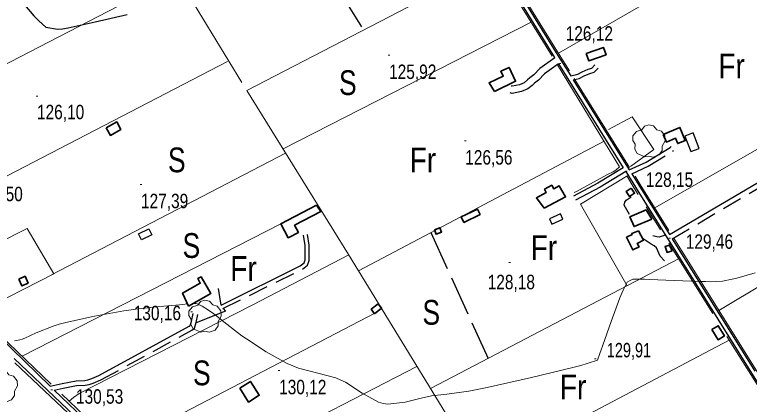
# Model space of a CAD drawing. Extents: x 487425 to 492029, y 4383576 to 4386788.
# Drawn here: x 489846.1 to 490290.9, y 4385229.4 to 4385465.2 of the extents above; entities that cross this region are included whole.
import ezdxf
from ezdxf.enums import TextEntityAlignment as Align

# ---------------------------------------------------------------- set-up
doc = ezdxf.new("R2010")
doc.units = 0
doc.header["$LTSCALE"] = 4
doc.linetypes.add('LONG_DASHED', pattern=[7.5, 6, -1.5])
doc.linetypes.add('MEDIUM_DASHED', pattern=[4.5, 3, -1.5])
for name, color, linetype, lineweight in [('21', 7, 'Continuous', 25), ('25', 7, 'LONG_DASHED', 25), ('29', 7, 'Continuous', 13), ('38', 7, 'Continuous', 25), ('47', 7, 'Continuous', 35), ('48', 7, 'MEDIUM_DASHED', 25), ('51', 7, 'Continuous', 13), ('7', 7, 'Continuous', 13), ('8', 7, 'Continuous', 25), ('9', 7, 'Continuous', 13)]:
    doc.layers.add(name, color=color, linetype=linetype, lineweight=lineweight)
doc.layers.add('31', color=7, linetype='Continuous')

msp = doc.modelspace()

# ---------------------------------------------------------------- linework, layer by layer
at = {"layer": '21'}
for points in [[(490251.81, 4385391.69), (490255.52, 4385382.34), (490260.49, 4385384.31), (490256.78, 4385393.66)], [(490176.54, 4385344.68), (490169.9, 4385341.62), (490171.35, 4385338.47), (490177.99, 4385341.53)]]:
    msp.add_lwpolyline(points, close=True, dxfattribs=at)
at = {"layer": '25'}
for p, q in [((489995.92, 4385554.6), (490057.22, 4385455.91)), ((490098.1, 4385333.38), (490132.67, 4385257.15))]:
    msp.add_line(p, q, dxfattribs=at)
at = {"layer": '29'}
for points in [[(490227.61, 4385379.12), (490223.07, 4385381.24), (490221.66, 4385383.78), (490221.76, 4385386.76), (490220.39, 4385389.17), (490220.43, 4385391.92), (490222.59, 4385394.52), (490225.78, 4385395.52), (490227.43, 4385397.71), (490230, 4385398.54), (490232.86, 4385397.89), (490234.81, 4385395.62), (490237.62, 4385394.8), (490239.75, 4385391.95), (490239.99, 4385388.82), (490238.11, 4385385.67), (490238.11, 4385382.99), (490236.29, 4385380.38), (490232.67, 4385379.04), (490229.9, 4385379.67)], [(489958.78, 4385273.08), (489954.24, 4385275.2), (489952.83, 4385277.74), (489952.93, 4385280.72), (489951.56, 4385283.13), (489951.6, 4385285.88), (489953.76, 4385288.48), (489956.95, 4385289.48), (489958.6, 4385291.67), (489961.17, 4385292.5), (489964.03, 4385291.85), (489965.98, 4385289.58), (489968.79, 4385288.76), (489970.92, 4385285.91), (489971.16, 4385282.78), (489969.28, 4385279.63), (489969.28, 4385276.95), (489967.46, 4385274.34), (489963.84, 4385273), (489961.07, 4385273.63)], [(489835.46, 4385230.87), (489830.92, 4385232.99), (489829.51, 4385235.53), (489829.61, 4385238.51), (489828.24, 4385240.92), (489828.28, 4385243.67), (489830.44, 4385246.27), (489833.63, 4385247.27), (489835.28, 4385249.46), (489837.85, 4385250.29), (489840.71, 4385249.64), (489842.66, 4385247.37), (489845.47, 4385246.55), (489847.6, 4385243.7), (489847.84, 4385240.57), (489845.96, 4385237.42), (489845.96, 4385234.74), (489844.14, 4385232.13), (489840.52, 4385230.79), (489837.75, 4385231.42)]]:
    msp.add_lwpolyline(points, close=True, dxfattribs=at)
at = {"layer": '38'}
for p, q in [((490175.43, 4385435.47), (490214.59, 4385372.6)), ((490184.26, 4385425.73), (490218.21, 4385371.23)), ((490244.19, 4385329.63), (490294.23, 4385249.56)), ((489971.09, 4385289.49), (489969.53, 4385299.42)), ((489836.23, 4385270.76), (489867.55, 4385240.41))]:
    msp.add_line(p, q, dxfattribs=at)
for points in [[(490091.34, 4385571.41), (490173.01, 4385439.35), (490173.19, 4385439.06)], [(490093.86, 4385571.79), (490175, 4385440.59), (490182.73, 4385428.18)], [(490173.19, 4385439.06), (490164.14, 4385432.69), (490160.43, 4385428.77), (490158.09, 4385426.95), (490156.66, 4385425.69), (490154.55, 4385424.06), (490151.66, 4385422.7), (490147.29, 4385421.91), (490146.71, 4385422.01)], [(490182.73, 4385428.18), (490186.96, 4385429.26), (490189.68, 4385430.68), (490193.37, 4385432.16), (490195.44, 4385432.88), (490197.31, 4385434.8)], [(490242.52, 4385332.29), (490309.11, 4385371.4), (490329.79, 4385383.31), (490335.95, 4385385.53), (490339.74, 4385386.46), (490342.83, 4385388.24)], [(490218.21, 4385371.23), (490228.37, 4385375.89), (490242.9, 4385384.93), (490243.56, 4385385.36)], [(490214.59, 4385372.6), (490199.14, 4385363.31), (490184.37, 4385355.43)], [(490216.06, 4385370.24), (490200.52, 4385360.89), (490185.68, 4385352.97)], [(490216.06, 4385370.24), (490221.96, 4385360.77), (490297.32, 4385240.19), (490301.58, 4385233.46)], [(490219.68, 4385368.86), (490223.95, 4385362.01), (490242.52, 4385332.29)], [(490218.3, 4385344.25), (490215.17, 4385349.96), (490215.47, 4385351.68), (490216.38, 4385352.88), (490219.31, 4385354.97)], [(489971.09, 4385289.49), (490019.01, 4385313.15), (490021.37, 4385315.09), (490022.03, 4385316.84), (490021.98, 4385325.6), (490021.03, 4385331.78)], [(490239.96, 4385331.89), (490236.33, 4385330.55), (490234.98, 4385330.71), (490232.43, 4385331.31)], [(490239.44, 4385316.22), (490236.97, 4385319.15), (490234.74, 4385324.18), (490233.17, 4385325.39), (490231.44, 4385326.37), (490226.06, 4385329.91)], [(489972.41, 4385287.51), (489973.84, 4385285.83), (489955.9, 4385278.66)], [(489867.55, 4385240.41), (489874.85, 4385242.08), (489883.26, 4385243.72), (489888.5, 4385243.86), (489890.41, 4385244.27), (489892.74, 4385244.99), (489897.09, 4385246.81), (489951.74, 4385276.67), (489952.43, 4385277.2), (489953.18, 4385279.58), (489954.08, 4385284.33)], [(489845.84, 4385257.08), (489890.1, 4385215.01), (489915.19, 4385191.17)], [(489870.05, 4385238.03), (489892.11, 4385217.12), (489919.37, 4385191.22)]]:
    msp.add_lwpolyline(points, dxfattribs=at)
at = {"layer": '38', "linetype": 'MEDIUM_DASHED'}
for points in [[(490175.43, 4385435.47), (490166.93, 4385429.47), (490163.29, 4385425.62), (490160.8, 4385423.69), (490159.36, 4385422.41), (490156.77, 4385420.42), (490152.97, 4385418.62), (490147.32, 4385417.61), (490146.02, 4385417.82)], [(490184.26, 4385425.73), (490187.95, 4385426.68), (490190.83, 4385428.18), (490194.33, 4385429.58), (490196.96, 4385430.5), (490199.28, 4385432.88)], [(490244.19, 4385329.63), (490310.69, 4385368.69), (490331.11, 4385380.46), (490336.85, 4385382.52), (490340.92, 4385383.53), (490344.39, 4385385.52)], [(490219.68, 4385368.86), (490229.68, 4385373.46), (490244.39, 4385382.61), (490245.07, 4385383.05)], [(489972.14, 4385287.38), (490020.29, 4385311.17), (490023.35, 4385313.67), (490024.38, 4385316.43), (490024.32, 4385325.78), (490023.36, 4385332.14)], [(489870.05, 4385238.03), (489875.44, 4385239.27), (489883.58, 4385240.85), (489888.85, 4385240.99), (489891.14, 4385241.49), (489893.72, 4385242.28), (489898.34, 4385244.22), (489953.31, 4385274.25), (489954.9, 4385275.47), (489955.97, 4385278.89), (489956.9, 4385283.8)]]:
    msp.add_lwpolyline(points, dxfattribs=at)
at = {"layer": '47'}
for points in [[(490192.05, 4385441.73), (490202.55, 4385445.41), (490204.12, 4385440.94), (490193.62, 4385437.26)], [(490136.5, 4385418.81), (490149.41, 4385424.91), (490145.42, 4385433.33), (490140.45, 4385430.98), (490141.85, 4385428), (490133.33, 4385424.01)], [(489901.52, 4385396.65), (489907.88, 4385400.28), (489910.44, 4385395.79), (489904.08, 4385392.16)], [(490238.69, 4385392.78), (490248.9, 4385396.95), (490252.12, 4385389.06), (490247.58, 4385387.21), (490246.26, 4385390.42), (490240.69, 4385388.13)], [(490166.65, 4385348.08), (490179.64, 4385354.94), (490175.8, 4385361.6), (490172.54, 4385359.74), (490171.23, 4385362.02), (490166.89, 4385359.54), (490167.94, 4385357.69), (490161.95, 4385354.31)], [(490219.4, 4385360.3), (490221.41, 4385357.19), (490218.33, 4385355.2), (490216.32, 4385358.31)], [(490028.84, 4385349.85), (490007.29, 4385338.67), (490011.67, 4385330.21), (490017.86, 4385333.42), (490015.59, 4385337.79), (490031.44, 4385346.04)], [(490116.47, 4385342.84), (490126.27, 4385347.61), (490127.88, 4385344.3), (490118.08, 4385339.53)], [(490231.94, 4385341.51), (490221.13, 4385336.97), (490218.61, 4385342.96), (490228.37, 4385347.08)], [(490100.25, 4385334.94), (490103.59, 4385336.24), (490104.6, 4385333.65), (490101.26, 4385332.35)], [(490223.82, 4385334.49), (490226.73, 4385328.71), (490223.01, 4385326.83), (490224.09, 4385324.67), (490220.4, 4385322.83), (490216.55, 4385330.54), (490219.95, 4385332.25), (490219.65, 4385332.83)], [(490244.25, 4385322.36), (490241.1, 4385321.32), (490239.92, 4385324.89), (490242.62, 4385325.8)], [(489848.62, 4385305.26), (489850.46, 4385301.13), (489854.22, 4385302.8), (489852.38, 4385306.93)], [(489951.36, 4385288.82), (489964.8, 4385296.43), (489959, 4385306.66), (489956.93, 4385305.5), (489958.49, 4385302.69), (489947.78, 4385296.75)], [(490063.96, 4385284.29), (490068.25, 4385287.55), (490066.23, 4385290.2), (490061.94, 4385286.94)], [(490268.18, 4385274.67), (490271.93, 4385268.47), (490275.81, 4385270.82), (490272.06, 4385277.02)], [(489982.32, 4385239.17), (489987.61, 4385230.8), (489994.16, 4385234.94), (489988.87, 4385243.31)]]:
    msp.add_lwpolyline(points, close=True, dxfattribs=at)
at = {"layer": '48'}
msp.add_lwpolyline([(489921.12, 4385332.63), (489927.34, 4385335.71), (489929.14, 4385332.08), (489922.92, 4385329)], close=True, dxfattribs=at)
at = {"layer": '51'}
for p, q in [((490091.15, 4385570.04), (490171.46, 4385440.19)), ((490175.37, 4385441.84), (490347.68, 4385541.46)), ((490158.83, 4385460.62), (490008.61, 4385383.94)), ((490233.65, 4385348.33), (490405.94, 4385447.02)), ((489773.46, 4385332.53), (489975.03, 4385436.91)), ((490212.32, 4385373.21), (490174.74, 4385434.91)), ((490218.36, 4385372.83), (490184.87, 4385426.58)), ((490202.92, 4385388.67), (490054.25, 4385310.24)), ((490010.13, 4385381.49), (489868.42, 4385307.8)), ((490391.9, 4385357.72), (490272.47, 4385286.22)), ((490237, 4385335.06), (490228.38, 4385348.85)), ((490007.29, 4385338.67), (489850.57, 4385258.5)), ((490268.7, 4385284.33), (490242.12, 4385326.86)), ((490248.04, 4385317.41), (490097.87, 4385238.96)), ((490064.57, 4385284.75), (489908.38, 4385203.59)), ((489868.22, 4385241.69), (489836.92, 4385271.49)), ((490129.55, 4385189.79), (490278.74, 4385268.28)), ((489938.76, 4385174.74), (490089.68, 4385252.35))]:
    msp.add_line(p, q, dxfattribs=at)
for points in [[(490094.71, 4385572.25), (490175.82, 4385441.1), (490181.98, 4385431.23)], [(490136.32, 4385497.01), (489986.69, 4385419.26), (490048.17, 4385320.17), (490113.16, 4385213.96), (490134.81, 4385182.02)], [(489831.21, 4385430.37), (489944.24, 4385488.89), (489983.56, 4385424.14)], [(490205.56, 4385395.8), (490219.9, 4385403.48), (490233.04, 4385383.65), (490218.84, 4385373.34)], [(490212.32, 4385373.21), (490210.06, 4385371.2), (490208.41, 4385370.15), (490205.1, 4385368.51), (490186.33, 4385358.22), (490184.83, 4385357.63)], [(490216.93, 4385301.16), (490188.7, 4385350.64), (490216.7, 4385367.57)], [(490223.66, 4385356.39), (490221.21, 4385360.3), (490216.62, 4385367.68)], [(490242.23, 4385334.59), (490224.77, 4385362.52), (490221.71, 4385367.44)], [(489799.67, 4385308.52), (489853.69, 4385335.81), (489869.74, 4385308.47), (489823.71, 4385285.06)], [(490314.35, 4385219.45), (490300.12, 4385241.95), (490245.13, 4385329.96)], [(489879.19, 4385231.29), (489881.68, 4385233.63), (489885.06, 4385236.01), (489989.97, 4385289.46), (490048.33, 4385319.92)], [(490299.79, 4385234.65), (490296.58, 4385239.72), (490277.3, 4385270.57)], [(489846.26, 4385254.56), (489889.09, 4385213.94), (489903.16, 4385200.59)], [(489874.63, 4385235.61), (489893.06, 4385218.12), (489918.13, 4385194.32)]]:
    msp.add_lwpolyline(points, dxfattribs=at)
at = {"layer": '7'}
for p, q in [((490072.26, 4385440.67), (490073.26, 4385440.67)), ((490175.86, 4385435.63), (490176.86, 4385435.63)), ((489859.09, 4385415.89), (489860.09, 4385415.89)), ((490118.36, 4385388.87), (490119.36, 4385388.87)), ((490215.93, 4385370.5), (490216.93, 4385370.5)), ((489922.06, 4385362.47), (489923.06, 4385362.47)), ((490242.2, 4385329.93), (490243.2, 4385329.93)), ((490145.36, 4385315.3), (490146.36, 4385315.3)), ((489952.79, 4385285.44), (489953.79, 4385285.44)), ((490197.14, 4385256.96), (490198.14, 4385256.96)), ((490005.7, 4385249.89), (490006.7, 4385249.89)), ((489867.92, 4385238.16), (489868.92, 4385238.16))]:
    msp.add_line(p, q, dxfattribs=at)
at = {"layer": '8'}
msp.add_lwpolyline([(489851.97, 4385471.2), (489857.8, 4385464.41), (489859.25, 4385462.87), (489860.63, 4385461.49), (489865.01, 4385457.72), (489871.98, 4385456.49), (489874.98, 4385456.7), (489878.45, 4385457.16), (489894.86, 4385460.81), (489914.12, 4385465.23)], dxfattribs=at)
at = {"layer": '9'}
for points in [[(490219.06, 4385304.64), (490220.34, 4385305.12), (490224.95, 4385305.2), (490227.41, 4385305.14), (490230.39, 4385305.03), (490245.4, 4385304.35), (490261.06, 4385303.73), (490264.44, 4385303.66), (490267.41, 4385303.64), (490274.69, 4385303.96), (490280.49, 4385305.11), (490282.52, 4385305.62), (490284.75, 4385306.21), (490294.33, 4385309.03)], [(489954.22, 4385290.44), (489954.96, 4385290.47), (489955.76, 4385290.35), (489956.58, 4385290.16), (489959.63, 4385288.91), (489963.55, 4385286.41), (489964.91, 4385285.43), (489966.38, 4385284.32), (489972.71, 4385279.25), (489980.98, 4385272.9), (489983.67, 4385270.97), (489986.55, 4385268.98), (489998.41, 4385261.19), (490011.11, 4385254.19), (490014.51, 4385252.7), (490017.86, 4385251.41), (490029.55, 4385248.34), (490040.58, 4385245.38), (490043.52, 4385244.15), (490046.4, 4385242.75), (490056.4, 4385236.23), (490066.28, 4385230.71), (490069.1, 4385229.95), (490071.95, 4385229.51), (490082.54, 4385230.68), (490092.98, 4385233.45), (490095.74, 4385234.02), (490098.44, 4385234.51), (490107.71, 4385235.57), (490120.97, 4385237.43), (490126.19, 4385238.42), (490132.08, 4385239.62), (490158.91, 4385245.68), (490184.05, 4385251.79), (490188.86, 4385253.02), (490192.75, 4385254.05), (490199.03, 4385256.09), (490200.42, 4385260.12), (490201.22, 4385262.41), (490202.21, 4385265.19), (490207.28, 4385279.45), (490212.57, 4385293.79), (490213.7, 4385296.62), (490214.68, 4385298.96), (490217, 4385303.29), (490218.33, 4385304.24), (490218.7, 4385304.45), (490219.06, 4385304.64)], [(489846.02, 4385267.78), (489849.32, 4385268.4), (489850.65, 4385268.87), (489852.17, 4385269.47), (489859.12, 4385272.74), (489869.47, 4385276.79), (489873.12, 4385277.89), (489877.11, 4385278.98), (489894.34, 4385282.82), (489912.24, 4385286.02), (489916.65, 4385286.7), (489920.83, 4385287.28), (489933.93, 4385288.66), (489943.75, 4385289.4), (489945.86, 4385289.59), (489947.71, 4385289.77), (489950.75, 4385290.17)]]:
    msp.add_lwpolyline(points, dxfattribs=at)

# ---------------------------------------------------------------- texts
at = {"layer": '31'}
for s, width, p in [('Fr', 0.85, (490280.17, 4385426.68)), ('S', 0.8, (490047.8, 4385416.57)), ('S', 0.8, (489944.24, 4385369.82)), ('Fr', 0.85, (490093.26, 4385369.82)), ('S', 0.8, (489953.09, 4385318.02)), ('Fr', 0.85, (490166.51, 4385316.76)), ('Fr', 0.85, (489984.65, 4385304.12)), ('S', 0.8, (490098.32, 4385277.59)), ('S', 0.8, (489959.4, 4385240.95)), ('Fr', 0.85, (490184.19, 4385232.42))]:
    msp.add_text(s, height=15, dxfattribs=dict(at, width=width)).set_placement(p, align=Align.CENTER)
at = {"layer": '7'}
for s, width, p in [('126,12', 0.8, (490179.68, 4385449.49)), ('125,92', 0.8, (490072.76, 4385426.3)), ('126,10', 0.8, (489859.59, 4385401.93)), ('126,56', 0.8, (490118.86, 4385374.5)), ('128,15', 0.8, (490228.24, 4385361.02)), ('127,50', 0.8, (489822.39, 4385352.33)), ('127,39', 0.8, (489922.56, 4385348.1)), ('129,46', 0.8, (490252.4, 4385323.53)), ('128,18', 0.8, (490132.46, 4385299.08)), ('130,16', 0.8, (489918.16, 4385280.32)), ('129,91', 0.75, (490204.58, 4385257.85)), ('130,12', 0.8, (490006.2, 4385235.52)), ('130,53', 0.8, (489883.21, 4385229.81))]:
    msp.add_text(s, height=8.75, dxfattribs=dict(at, width=width)).set_placement(p)

doc.saveas('drawing.dxf')
